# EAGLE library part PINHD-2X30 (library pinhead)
PIN HEADER
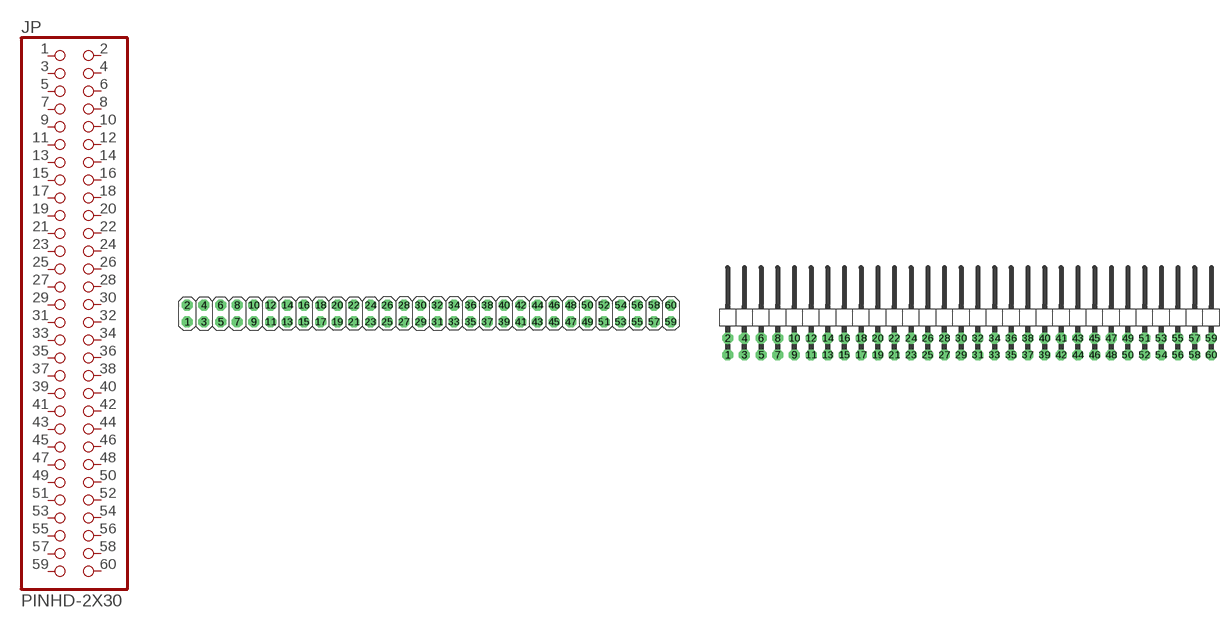
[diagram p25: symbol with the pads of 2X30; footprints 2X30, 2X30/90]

Designator prefix JP

## PINHD-2X30  [2X30]
1  1  pas
2  2  pas
3  3  pas
4  4  pas
5  5  pas
6  6  pas
7  7  pas
8  8  pas
9  9  pas
10  10  pas
11  11  pas
12  12  pas
13  13  pas
14  14  pas
15  15  pas
16  16  pas
17  17  pas
18  18  pas
19  19  pas
20  20  pas
21  21  pas
22  22  pas
23  23  pas
24  24  pas
25  25  pas
26  26  pas
27  27  pas
28  28  pas
29  29  pas
30  30  pas
31  31  pas
32  32  pas
33  33  pas
34  34  pas
35  35  pas
36  36  pas
37  37  pas
38  38  pas
39  39  pas
40  40  pas
41  41  pas
42  42  pas
43  43  pas
44  44  pas
45  45  pas
46  46  pas
47  47  pas
48  48  pas
49  49  pas
50  50  pas
51  51  pas
52  52  pas
53  53  pas
54  54  pas
55  55  pas
56  56  pas
57  57  pas
58  58  pas
59  59  pas
60  60  pas

## PINHD-2X30/90  [2X30/90]
Pads as for 2X30

## Footprint 2X30 (pad centres in mm)
PIN HEADER
drill 1.016 pad 1.67 octagon: 1 -38.1,-1.27; 2 -38.1,1.27; 3 -35.56,-1.27; 4 -35.56,1.27; 5 -33.02,-1.27; 6 -33.02,1.27; 7 -30.48,-1.27; 8 -30.48,1.27; 9 -27.94,-1.27; 10 -27.94,1.27; 11 -25.4,-1.27; 12 -25.4,1.27; 13 -22.86,-1.27; 14 -22.86,1.27; 15 -20.32,-1.27; 16 -20.32,1.27; 17 -17.78,-1.27; 18 -17.78,1.27; 19 -15.24,-1.27; 20 -15.24,1.27; 21 -12.7,-1.27; 22 -12.7,1.27; 23 -10.16,-1.27; 24 -10.16,1.27; 25 -7.62,-1.27; 26 -7.62,1.27; 27 -5.08,-1.27; 28 -5.08,1.27; 29 -2.54,-1.27; 30 -2.54,1.27; 31 0,-1.27; 32 0,1.27; 33 2.54,-1.27; 34 2.54,1.27; 35 5.08,-1.27; 36 5.08,1.27; 37 7.62,-1.27; 38 7.62,1.27; 39 10.16,-1.27; 40 10.16,1.27; 41 12.7,-1.27; 42 12.7,1.27; 43 15.24,-1.27; 44 15.24,1.27; 45 17.78,-1.27; 46 17.78,1.27; 47 20.32,-1.27; 48 20.32,1.27; 49 22.86,-1.27; 50 22.86,1.27; 51 25.4,-1.27; 52 25.4,1.27; 53 27.94,-1.27; 54 27.94,1.27; 55 30.48,-1.27; 56 30.48,1.27; 57 33.02,-1.27; 58 33.02,1.27; 59 35.56,-1.27; 60 35.56,1.27

## Footprint 2X30/90 (pad centres in mm)
PIN HEADER
drill 1.016 pad 1.67 octagon: 1 -36.83,-6.35; 2 -36.83,-3.81; 3 -34.29,-6.35; 4 -34.29,-3.81; 5 -31.75,-6.35; 6 -31.75,-3.81; 7 -29.21,-6.35; 8 -29.21,-3.81; 9 -26.67,-6.35; 10 -26.67,-3.81; 11 -24.13,-6.35; 12 -24.13,-3.81; 13 -21.59,-6.35; 14 -21.59,-3.81; 15 -19.05,-6.35; 16 -19.05,-3.81; 17 -16.51,-6.35; 18 -16.51,-3.81; 19 -13.97,-6.35; 20 -13.97,-3.81; 21 -11.43,-6.35; 22 -11.43,-3.81; 23 -8.89,-6.35; 24 -8.89,-3.81; 25 -6.35,-6.35; 26 -6.35,-3.81; 27 -3.81,-6.35; 28 -3.81,-3.81; 29 -1.27,-6.35; 30 -1.27,-3.81; 31 1.27,-6.35; 32 1.27,-3.81; 33 3.81,-6.35; 34 3.81,-3.81; 35 6.35,-6.35; 36 6.35,-3.81; 37 8.89,-6.35; 38 8.89,-3.81; 39 11.43,-6.35; 40 11.43,-3.81; 41 13.97,-3.81; 42 13.97,-6.35; 43 16.51,-3.81; 44 16.51,-6.35; 45 19.05,-3.81; 46 19.05,-6.35; 47 21.59,-3.81; 48 21.59,-6.35; 49 24.13,-3.81; 50 24.13,-6.35; 51 26.67,-3.81; 52 26.67,-6.35; 53 29.21,-3.81; 54 29.21,-6.35; 55 31.75,-3.81; 56 31.75,-6.35; 57 34.29,-3.81; 58 34.29,-6.35; 59 36.83,-3.81; 60 36.83,-6.35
